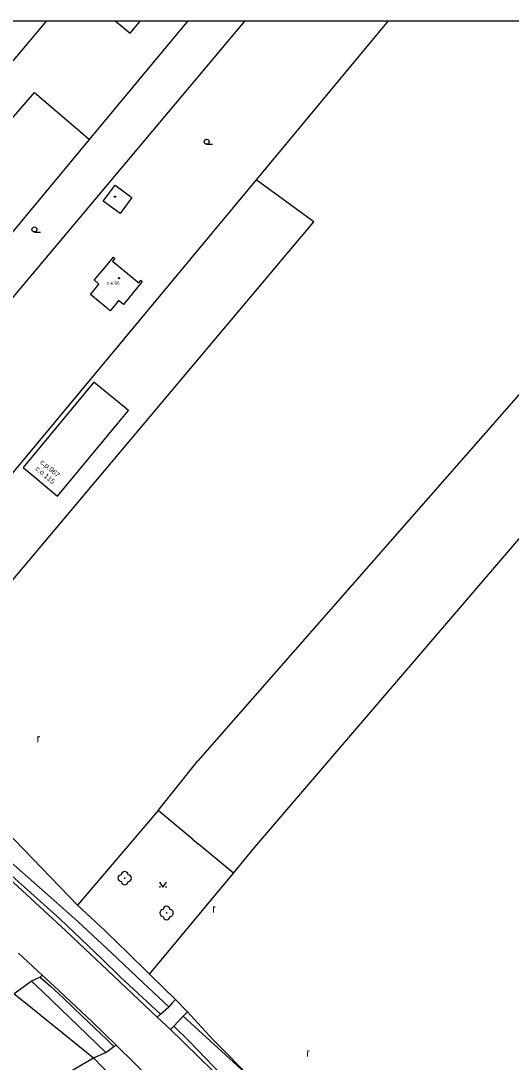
# Model space of a CAD drawing. Extents: x -594386 to -594050, y -1167541 to -1167175.
# Drawn here: x -594263.8 to -594190.8, y -1167330.4 to -1167175.4 of the extents above; entities that cross this region are included whole.
import ezdxf

# ---------------------------------------------------------------- set-up
doc = ezdxf.new("R2010")
doc.units = 0
for name, color, linetype in [('Level 14', 7, 'Continuous'), ('Level 22', 7, 'Continuous'), ('Level 36', 7, 'Continuous'), ('Level 39', 7, 'Continuous'), ('Vrstva 1', 7, 'Continuous'), ('Vrstva 10', 7, 'Continuous'), ('Vrstva 11', 7, 'Continuous'), ('Vrstva 46', 7, 'Continuous'), ('Vrstva 51', 7, 'Continuous'), ('Vrstva 52', 7, 'Continuous'), ('Vrstva 63', 7, 'Continuous'), ('Vrstva 7', 7, 'Continuous'), ('Vrstva 8', 7, 'Continuous')]:
    doc.layers.add(name, color=color, linetype=linetype)

msp = doc.modelspace()

# ---------------------------------------------------------------- linework, layer by layer
at = {"layer": 'Level 14'}
for points in [[(-594251.18, -1167328.94), (-594260.61, -1167319.87), (-594262.22, -1167318.36)], [(-594239.66, -1167323.56), (-594229.34, -1167332.99)]]:
    msp.add_lwpolyline(points, dxfattribs=at)
at = {"layer": 'Level 22'}
for centre in [(-594248.36, -1167303.02), (-594242.12, -1167308.2)]:
    msp.add_circle(centre, 0.05, dxfattribs=at)
for centre, start, end in [((-594248.36, -1167302.52), 0, 180), ((-594248.86, -1167303.02), 90, 270), ((-594248.36, -1167303.52), 180, 0), ((-594247.86, -1167303.02), 270, 90), ((-594242.62, -1167308.2), 90, 270), ((-594242.12, -1167307.7), 0, 180), ((-594241.62, -1167308.2), 270, 90), ((-594242.12, -1167308.7), 180, 0)]:
    msp.add_arc(centre, 0.5, start, end, dxfattribs=at)
at = {"layer": 'Level 36'}
for p, q in [((-594236.16, -1167193.8), (-594235.28, -1167193.8)), ((-594261.79, -1167206.86), (-594260.91, -1167206.86))]:
    msp.add_line(p, q, dxfattribs=at)
msp.add_lwpolyline([(-594243.16, -1167303.63), (-594242.66, -1167304.38), (-594242.16, -1167303.63)], dxfattribs=at)
for centre, radius in [((-594236.16, -1167193.43), 0.375), ((-594261.79, -1167206.48), 0.375), ((-594243.11, -1167304.33), 0.05), ((-594242.21, -1167304.33), 0.05)]:
    msp.add_circle(centre, radius, dxfattribs=at)
at = {"layer": 'Level 39'}
for centre, radius in [((-594249.81, -1167201.6), 0.09), ((-594249.81, -1167201.6), 0.0398), ((-594249.2, -1167213.72), 0.09), ((-594249.2, -1167213.72), 0.0398)]:
    msp.add_circle(centre, radius, dxfattribs=at)
at = {"layer": 'Vrstva 1'}
msp.add_lwpolyline([(-594266.03, -1167295.95), (-594255.36, -1167307.05)], dxfattribs=at)
at = {"layer": 'Vrstva 10'}
for points in [[(-594288.58, -1167283.24), (-594279.44, -1167290.95), (-594274.82, -1167294.9), (-594269.08, -1167299.96), (-594265.51, -1167303.14), (-594257.18, -1167310.82), (-594254.25, -1167313.59)], [(-594264.15, -1167314.19), (-594260.63, -1167317.44)], [(-594254.25, -1167313.59), (-594251.83, -1167315.87)], [(-594251.83, -1167315.87), (-594243.51, -1167323.68)], [(-594260.63, -1167317.44), (-594258.84, -1167319.1)], [(-594258.84, -1167319.1), (-594253.22, -1167324.41), (-594249.64, -1167327.86)], [(-594243.51, -1167323.68), (-594241.53, -1167325.54)], [(-594241.53, -1167325.54), (-594239.65, -1167327.35), (-594235.19, -1167331.75), (-594229.59, -1167337.47), (-594226.74, -1167340.41), (-594223.76, -1167343.56), (-594214.14, -1167353.82), (-594205.68, -1167362.85), (-594194.93, -1167374.34)], [(-594249.64, -1167327.86), (-594244.05, -1167333.32)]]:
    msp.add_lwpolyline(points, dxfattribs=at)
at = {"layer": 'Vrstva 11'}
for points in [[(-594249.77, -1167175.43), (-594247.55, -1167177.28), (-594246.03, -1167175.43)], [(-594315.46, -1167248.23), (-594261.8, -1167186.09)], [(-594261.8, -1167186.09), (-594253.6, -1167193.11)], [(-594269.21, -1167263.56), (-594220.22, -1167205.32), (-594228.81, -1167199.11)], [(-594251.46, -1167212.32), (-594250.02, -1167210.62), (-594249.83, -1167210.78), (-594250.17, -1167211.19)], [(-594252.82, -1167214.08), (-594252.9, -1167214.01), (-594251.46, -1167212.32)], [(-594250.17, -1167211.19), (-594246.25, -1167214.4), (-594245.94, -1167214.04), (-594245.74, -1167214.22), (-594248.55, -1167217.66), (-594249.29, -1167217.05), (-594249.55, -1167217.38)], [(-594249.55, -1167217.38), (-594250.53, -1167218.59), (-594253.47, -1167216.15), (-594252.57, -1167215.06)], [(-594252.57, -1167215.06), (-594252.21, -1167214.63), (-594252.82, -1167214.08)], [(-594263.48, -1167241.92), (-594258.37, -1167246.16), (-594247.8, -1167233.4), (-594252.94, -1167229.2), (-594263.48, -1167241.92)], [(-594250.33, -1167314.14), (-594255.34, -1167309.45), (-594259.37, -1167305.89), (-594267.41, -1167298.85), (-594273.09, -1167293.97), (-594278.06, -1167289.69), (-594284.33, -1167284.3), (-594285.35, -1167282.85), (-594285.74, -1167281.65), (-594286.57, -1167279.54)], [(-594288.39, -1167282.73), (-594281.26, -1167288.77), (-594277.31, -1167292.1), (-594273.99, -1167294.9), (-594268.56, -1167299.65), (-594257.99, -1167309.09), (-594251.7, -1167315.09)], [(-594243.38, -1167292.96), (-594255.36, -1167307.05)], [(-594244.68, -1167317.3), (-594232.17, -1167302.25)], [(-594255.36, -1167307.05), (-594251.25, -1167310.84)], [(-594251.25, -1167310.84), (-594249.16, -1167312.87)], [(-594249.16, -1167312.87), (-594248.13, -1167313.9), (-594244.68, -1167317.3)], [(-594250.33, -1167314.14), (-594245.64, -1167318.55)], [(-594251.7, -1167315.09), (-594249.01, -1167317.68), (-594243.04, -1167323.26)], [(-594260.63, -1167317.44), (-594260.95, -1167317.73)], [(-594244.68, -1167317.3), (-594244.63, -1167317.35), (-594240.81, -1167321.05)], [(-594262.22, -1167318.36), (-594263.37, -1167319.2), (-594264.81, -1167320.21)], [(-594260.95, -1167317.73), (-594262.22, -1167318.36)], [(-594260.95, -1167317.73), (-594259.39, -1167319.09), (-594257.53, -1167320.84), (-594254.64, -1167323.59), (-594251.03, -1167327.04), (-594249.99, -1167328.06)], [(-594245.64, -1167318.55), (-594241.81, -1167322.16)], [(-594243.04, -1167323.26), (-594241.81, -1167322.16)], [(-594241.22, -1167321.5), (-594241.81, -1167322.16)], [(-594240.81, -1167321.05), (-594241.22, -1167321.5)], [(-594239.03, -1167322.92), (-594240.81, -1167321.05)], [(-594243.04, -1167323.26), (-594243.51, -1167323.68)], [(-594239.66, -1167323.56), (-594241.06, -1167325.06)], [(-594239.03, -1167322.92), (-594239.66, -1167323.56)], [(-594229.34, -1167332.99), (-594235.08, -1167327.19), (-594236.4, -1167325.79), (-594239.03, -1167322.92)], [(-594241.06, -1167325.06), (-594241.53, -1167325.54)], [(-594241.06, -1167325.06), (-594238.77, -1167327.25), (-594226.55, -1167339.98), (-594212.97, -1167354.25), (-594205.48, -1167362.18), (-594194.21, -1167374.23)], [(-594251.18, -1167328.94), (-594249.99, -1167328.06)], [(-594249.99, -1167328.06), (-594249.64, -1167327.86)], [(-594252.98, -1167329.77), (-594251.18, -1167328.94)]]:
    msp.add_lwpolyline(points, dxfattribs=at)
at = {"layer": 'Vrstva 51'}
for p, q in [((-594230.48, -1167175.43), (-594298.65, -1167256.55)), ((-594253.6, -1167193.11), (-594238.93, -1167175.43)), ((-594229, -1167298.38), (-594123.58, -1167175.43)), ((-594209.17, -1167175.43), (-594228.81, -1167199.11))]:
    msp.add_line(p, q, dxfattribs=at)
for points in [[(-594149.13, -1167184.83), (-594237.46, -1167285.58)], [(-594306.69, -1167257.1), (-594253.6, -1167193.11)], [(-594228.81, -1167199.11), (-594267.95, -1167246.12)], [(-594363.06, -1167394.04), (-594252.98, -1167329.77)]]:
    msp.add_lwpolyline(points, dxfattribs=at)
at = {"layer": 'Vrstva 52'}
for points in [[(-594251.54, -1167202.29), (-594249.77, -1167199.88)], [(-594249.77, -1167199.88), (-594247.28, -1167201.71)], [(-594249.05, -1167204.12), (-594251.54, -1167202.29)], [(-594247.28, -1167201.71), (-594249.05, -1167204.12)]]:
    msp.add_lwpolyline(points, dxfattribs=at)
at = {"layer": 'Vrstva 63'}
msp.add_lwpolyline([(-594386.36, -1167175.43), (-594049.75, -1167175.43), (-594049.75, -1167540.79), (-594386.36, -1167540.79)], close=True, dxfattribs=at)
at = {"layer": 'Vrstva 7'}
msp.add_line((-594259.98, -1167175.43), (-594266.27, -1167182.94), dxfattribs=at)
for points in [[(-594240.59, -1167289.48), (-594237.46, -1167285.58)], [(-594243.38, -1167292.96), (-594240.59, -1167289.48)], [(-594238.33, -1167297.16), (-594243.38, -1167292.96)], [(-594232.17, -1167302.25), (-594237.39, -1167297.97)], [(-594232.17, -1167302.25), (-594229, -1167298.38)], [(-594264.81, -1167320.21), (-594263.14, -1167321.56)], [(-594263.14, -1167321.56), (-594252.98, -1167329.77)]]:
    msp.add_lwpolyline(points, dxfattribs=at)
at = {"layer": 'Vrstva 8'}
for points in [[(-594238.33, -1167297.16), (-594237.39, -1167297.97)], [(-594252.98, -1167329.77), (-594250.3, -1167332.52)]]:
    msp.add_lwpolyline(points, dxfattribs=at)

# ---------------------------------------------------------------- texts
at = {"layer": 'Level 36'}
for p in [(-594261.46, -1167282.79), (-594235.33, -1167308.13), (-594221.35, -1167329.57)]:
    msp.add_text('r', height=1.2, dxfattribs=at).set_placement(p)
at = {"layer": 'Vrstva 46'}
msp.add_text('c.e.96', height=0.5, dxfattribs=at).set_placement((-594251, -1167214.71))
for s, p in [('c.p.967', (-594261, -1167241.23)), ('c.o.115', (-594261.72, -1167242.21))]:
    msp.add_text(s, height=0.75, rotation=319.6583, dxfattribs=at).set_placement(p)

doc.saveas('drawing.dxf')
